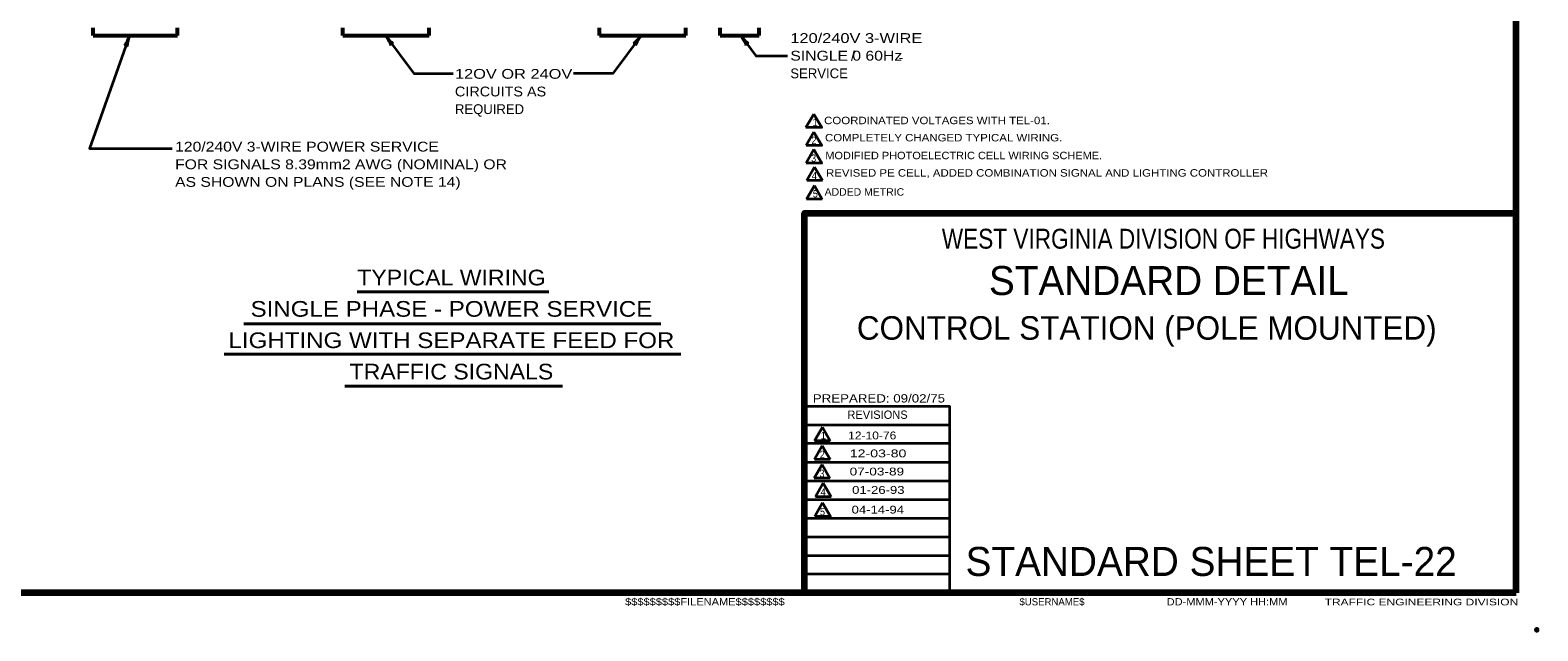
# Model space of a CAD drawing. Extents: x -35 to 821, y -18 to 526.
# Drawn here: x 359.2 to 821, y -18.5 to 165.4 of the extents above; entities that cross this region are included whole.
import ezdxf
from ezdxf.enums import TextEntityAlignment as Align

# ---------------------------------------------------------------- set-up
doc = ezdxf.new("R2010")
doc.units = 0
doc.header["$LTSCALE"] = 1.2
doc.header["$PDMODE"] = 32
doc.header["$PDSIZE"] = 0.6
doc.layers.add('1', color=7, linetype='Continuous', lineweight=53)
doc.layers.add('61', color=7, linetype='Continuous', lineweight=35)

msp = doc.modelspace()

# ---------------------------------------------------------------- linework, layer by layer
at = {"layer": '1', "lineweight": 158}
for q in [(814.433, 519.216), (814.433, 109.416), (22.833, -6.884)]:
    msp.add_line((814.433, -6.884), q, dxfattribs=at)
at = {"layer": '1', "lineweight": 13}
msp.add_line((814.433, -6.884), (814.433, 519.216), dxfattribs=at)
at = {"layer": '1'}
for p, q in [((378.525, 163.757), (378.525, 166.157)), ((378.525, 163.757), (404.325, 163.757)), ((404.325, 163.757), (404.325, 166.157)), ((455.025, 163.757), (455.025, 166.157)), ((455.025, 163.757), (481.425, 163.757)), ((481.425, 163.757), (481.425, 166.157)), ((533.625, 163.757), (533.625, 166.157)), ((533.625, 163.757), (560.025, 163.757)), ((560.025, 163.757), (560.025, 166.157)), ((570.525, 163.757), (570.525, 166.157)), ((570.525, 163.757), (582.525, 163.757)), ((582.525, 163.757), (582.525, 166.157))]:
    msp.add_line(p, q, dxfattribs=at)
at = {"layer": '1', "lineweight": 35}
for p, q in [((599.255, 139.738), (596.855, 135.581)), ((599.27, 134.212), (596.87, 130.055)), ((599.262, 128.835), (596.862, 124.678)), ((599.471, 123.507), (597.071, 119.35)), ((599.471, 123.507), (601.871, 119.35)), ((599.413, 117.855), (597.013, 113.699)), ((601.871, 119.35), (597.071, 119.35)), ((599.413, 117.855), (601.813, 113.699)), ((601.813, 113.699), (597.013, 113.699)), ((640.933, 44.516), (596.433, 44.516)), ((601.896, 43.882), (599.496, 39.725)), ((601.896, 43.882), (604.296, 39.725)), ((640.933, 38.816), (596.433, 38.816)), ((601.858, 38.106), (599.458, 33.949)), ((604.296, 39.725), (599.496, 39.725)), ((601.858, 38.106), (604.258, 33.949)), ((640.933, 33.016), (596.433, 33.016)), ((601.798, 32.428), (599.398, 28.271)), ((604.258, 33.949), (599.458, 33.949)), ((601.798, 32.428), (604.198, 28.271)), ((604.198, 28.271), (599.398, 28.271)), ((640.933, 27.316), (596.433, 27.316)), ((602.119, 26.74), (599.719, 22.583)), ((602.119, 26.74), (604.519, 22.583)), ((640.933, 21.616), (596.433, 21.616)), ((601.961, 20.716), (599.561, 16.559)), ((604.519, 22.583), (599.719, 22.583)), ((640.933, 15.916), (596.433, 15.916)), ((640.933, 10.216), (596.433, 10.216)), ((640.933, 4.516), (596.433, 4.516)), ((640.933, -1.184), (596.433, -1.184))]:
    msp.add_line(p, q, dxfattribs=at)
at = {"layer": '1', "lineweight": 40}
for p, q in [((459.362, 85.262), (518.034, 85.262)), ((424.605, 75.502), (552.368, 75.502)), ((418.66, 66.2), (558.498, 66.2)), ((455.551, 56.441), (522.287, 56.441))]:
    msp.add_line(p, q, dxfattribs=at)
at = {"layer": '1', "lineweight": 35}
for points in [[(389.657, 163.757), (377.399, 129.2), (402.669, 129.2)], [(468.035, 163.759), (476.737, 152.114), (488.732, 152.114)], [(546.353, 163.759), (537.651, 152.114), (525.656, 152.114)], [(576.874, 163.759), (581.503, 157.564), (591.146, 157.564)], [(599.255, 139.738), (601.655, 135.581), (596.855, 135.581)], [(599.27, 134.212), (601.67, 130.055), (596.87, 130.055)], [(599.262, 128.835), (601.662, 124.678), (596.862, 124.678)], [(640.933, -6.884), (640.933, 50.216), (596.433, 50.216)], [(601.961, 20.716), (604.361, 16.559), (599.561, 16.559)]]:
    msp.add_lwpolyline(points, dxfattribs=at)
at = {"layer": '1', "lineweight": 158}
msp.add_lwpolyline([(596.433, -6.884), (596.433, 109.416), (814.433, 109.416)], dxfattribs=at)
at = {"layer": '1', "lineweight": 40}
for centre, major_axis, ratio, start_param, end_param in [((388.968, 162.575), (0.903, 1.916), 0.07063, 3.1407148, 5.41811), ((389.532, 162.412), (0.54, 2.082), 0.122415, 0.8963533, 3.1415927), ((468.637, 162.53), (1.093, -1.815), 0.07063, 6.2823074, 8.5597026), ((469.085, 162.909), (-1.433, 1.604), 0.122415, 0.8963533, 3.1415927), ((545.303, 162.909), (1.433, 1.604), 0.122415, 3.1415927, 5.386832), ((545.751, 162.53), (-1.093, -1.815), 0.07063, 4.006668, 6.2840632), ((577.475, 162.53), (1.093, -1.815), 0.07063, 6.2823074, 8.5597026), ((577.923, 162.909), (-1.433, 1.604), 0.122415, 0.8963533, 3.1415927)]:
    msp.add_ellipse(centre, major_axis=major_axis, ratio=ratio, start_param=start_param, end_param=end_param, dxfattribs=at)
at = {"layer": '1'}
msp.add_point((820.733, -18.184), dxfattribs=at)
at = {"layer": '61', "lineweight": 53}
for q in [(661.733, -6.884), (661.733, -6.884), (661.733, -6.884), (662.033, -6.884), (662.033, -6.884)]:
    msp.add_line((814.433, -6.884), q, dxfattribs=at)

# ---------------------------------------------------------------- texts
at = {"layer": '1'}
for s, height, width, p in [('120/240V 3-WIRE', 3, 1.25, (592.06, 161.488)), ('SINGLE 0 60Hz', 3, 1.2, (592.06, 156.088)), ('12OV OR 24OV', 3, 1.25, (489.32, 150.525)), ('CIRCUITS AS', 3, 1.1, (489.32, 145.125)), ('COORDINATED VOLTAGES WITH TEL-01.', 2.28, 1.15, (602.4, 136.618)), ('120/240V 3-WIRE POWER SERVICE', 3, 1.2, (403.598, 128.245)), ('2', 2.28, 0.9, (598.52, 130.517)), ('COMPLETELY CHANGED TYPICAL WIRING.', 2.28, 1.15, (602.678, 131.349)), ('FOR SIGNALS 8.39mm2 AWG (NOMINAL) OR', 3, 1.2, (403.598, 122.845)), ('3', 2.28, 0.9, (598.427, 125.064)), ('MODIFIED PHOTOELECTRIC CELL WIRING SCHEME.', 2.28, 1.1, (602.77, 125.896)), ('AS SHOWN ON PLANS (SEE NOTE 14)', 3, 1.2, (403.598, 117.445)), ('4', 2.28, 0.95, (598.636, 119.736)), ('REVISED PE CELL, ADDED COMBINATION SIGNAL AND LIGHTING CONTROLLER', 2.28, 1.15, (602.979, 120.568)), ('5', 2.28, 0.9, (598.955, 114.181)), ('ADDED METRIC', 2.28, 1.05, (602.559, 114.735)), ('PREPARED: 09/02/75', 2.537, 1.2, (598.933, 51.416)), ('2', 2.28, 0.9, (601.092, 34.377)), ('3', 2.28, 0.9, (600.984, 28.551)), ('4', 2.28, 0.95, (601.305, 22.863)), ('5', 2.28, 0.9, (601.147, 16.839)), ('$$$$$$$$$FILENAME$$$$$$$$', 2.2, 1.15, (541.433, -10.684)), ('DD-MMM-YYYY HH:MM', 2.2, 1.15, (707.333, -10.684)), ('TRAFFIC ENGINEERING DIVISION', 2.031, 1.35, (755.733, -10.684))]:
    msp.add_text(s, height=height, dxfattribs=dict(at, width=width)).set_placement(p)
for s, height, p in [('/', 3, (610.655, 156.032)), ('SERVICE', 3, (592.06, 150.688)), ('-', 3, (625.262, 155.545)), ('REQUIRED', 3, (489.32, 139.725)), ('1', 2.28, (598.797, 136.063)), ('CONTROL STATION (POLE MOUNTED)', 7.2, (612.437, 70.642)), ('REVISIONS', 2.537, (609.533, 46.416)), ('1', 2.28, (601.328, 40.153)), ('STANDARD SHEET TEL-22', 8.881, (645.733, -1.684)), ('$USERNAME$', 2.2, (662.233, -10.684))]:
    msp.add_text(s, height=height, dxfattribs=at).set_placement(p)
for s, height, width, p in [('WEST VIRGINIA DIVISION OF HIGHWAYS', 6.089, 0.85, (706.333, 98.516)), ('TYPICAL WIRING', 4.8, 1.1, (488.244, 87.274)), ('SINGLE PHASE - POWER SERVICE', 4.8, 1.15, (488.244, 77.674)), ('LIGHTING WITH SEPARATE FEED FOR', 4.8, 1.15, (488.244, 68.074)), ('TRAFFIC SIGNALS', 4.8, 1.1, (488.244, 58.474)), ('12-10-76', 2.4, 1.15, (617.142, 40.13)), ('12-03-80 ', 2.4, 1.35, (619.538, 34.631)), ('07-03-89', 2.4, 1.3, (618.568, 29.084)), ('01-26-93', 2.4, 1.25, (619.007, 23.439)), ('04-14-94', 2.4, 1.25, (618.858, 17.414))]:
    msp.add_text(s, height=height, dxfattribs=dict(at, width=width)).set_placement(p, align=Align.CENTER)
msp.add_text('STANDARD DETAIL', height=8.881, dxfattribs=at).set_placement((707.983, 84.316), align=Align.CENTER)

doc.saveas('drawing.dxf')
